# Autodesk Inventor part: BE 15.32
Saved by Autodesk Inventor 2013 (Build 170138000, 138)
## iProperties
Created: 2012-12
Part Number: BE 15.32
Material: Générique
Document SubType Name: Modeling
Designer: jost thierry
Density: 1 g/cm^3
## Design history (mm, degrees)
node "BE 15.321"
node "BE 15.32"
node "Base1"
